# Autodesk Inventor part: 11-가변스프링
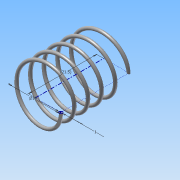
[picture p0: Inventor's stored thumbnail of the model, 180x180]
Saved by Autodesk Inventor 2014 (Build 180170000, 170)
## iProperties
Created: 2015-06
Part Number: 11-가변스프링
Material: 강철, 연강
Document SubType Name: Modeling
Designer: MYHOME
Density: 7.86 g/cm^3
Appearance: 강철
Mass: 1.53479 g
Surface Area: 7.89194 cm^2
Volume: 0.195266 cm^3
Author: MYHOME
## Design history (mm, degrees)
sketch "스케치1"
  geometry: L1 (0, 21.5)-(8, 21.5); L2 (8, 21.5)-(8, 0); L3 (8, 0)-(0, 0); L4 (0, 0)-(0, 21.5); C1 r 0.5 at (8, 0); 1 further point
  constraints: 8 end point, 3 coincident, 2 parallel, 1 centre point, 1 horizontal, 1 perpendicular
  dimensions: "d0" = 1 diameter of C1; "d1" = 16 diameter of L2 L4; "d2" = 21.5 distance of L3.end L1.start (derived)
feature "코일1" sketch "스케치1" pitch "d3" = 10; turns "d5" = 5; dims "d4" = 21.5 (= d2), "d6" = 0, angle "d7" = 90 deg, angle "d8" = 90 deg, "d9" = 0, "d10" = 0
sketch "스케치2"
  geometry: L1 (-8.5, 0)-(-7.5, 0) reference; 1 further point
  constraints: 1 horizontal alignment
extrude "돌출1" cut sketch "스케치2" stored distance "d11" = 10; taper "d12" = 0 deg
node "작업 평면1"
sketch "스케치3"
  geometry: L1 (-7.5, 0)-(-8.5, 0) reference; 1 further point
  constraints: 1 horizontal alignment
extrude "돌출2" cut sketch "스케치3" stored distance "d14" = 10; taper "d15" = 0 deg
node "솔리드1"
node "절단 모서리 투영1"
node "절단 모서리 투영2"
other parameters: "d13" = 21.5 (= d2)
